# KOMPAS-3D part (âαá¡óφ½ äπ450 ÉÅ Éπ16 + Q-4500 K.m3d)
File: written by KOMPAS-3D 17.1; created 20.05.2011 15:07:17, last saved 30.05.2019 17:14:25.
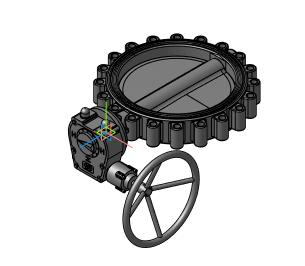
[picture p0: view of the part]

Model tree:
1. Плоскость XY
2. Плоскость ZX
3. Плоскость ZY
4. Ось X
5. Ось Y
6. Ось Z
7. Начало координат
8. Операция без истории:3

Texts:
  Viktor2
